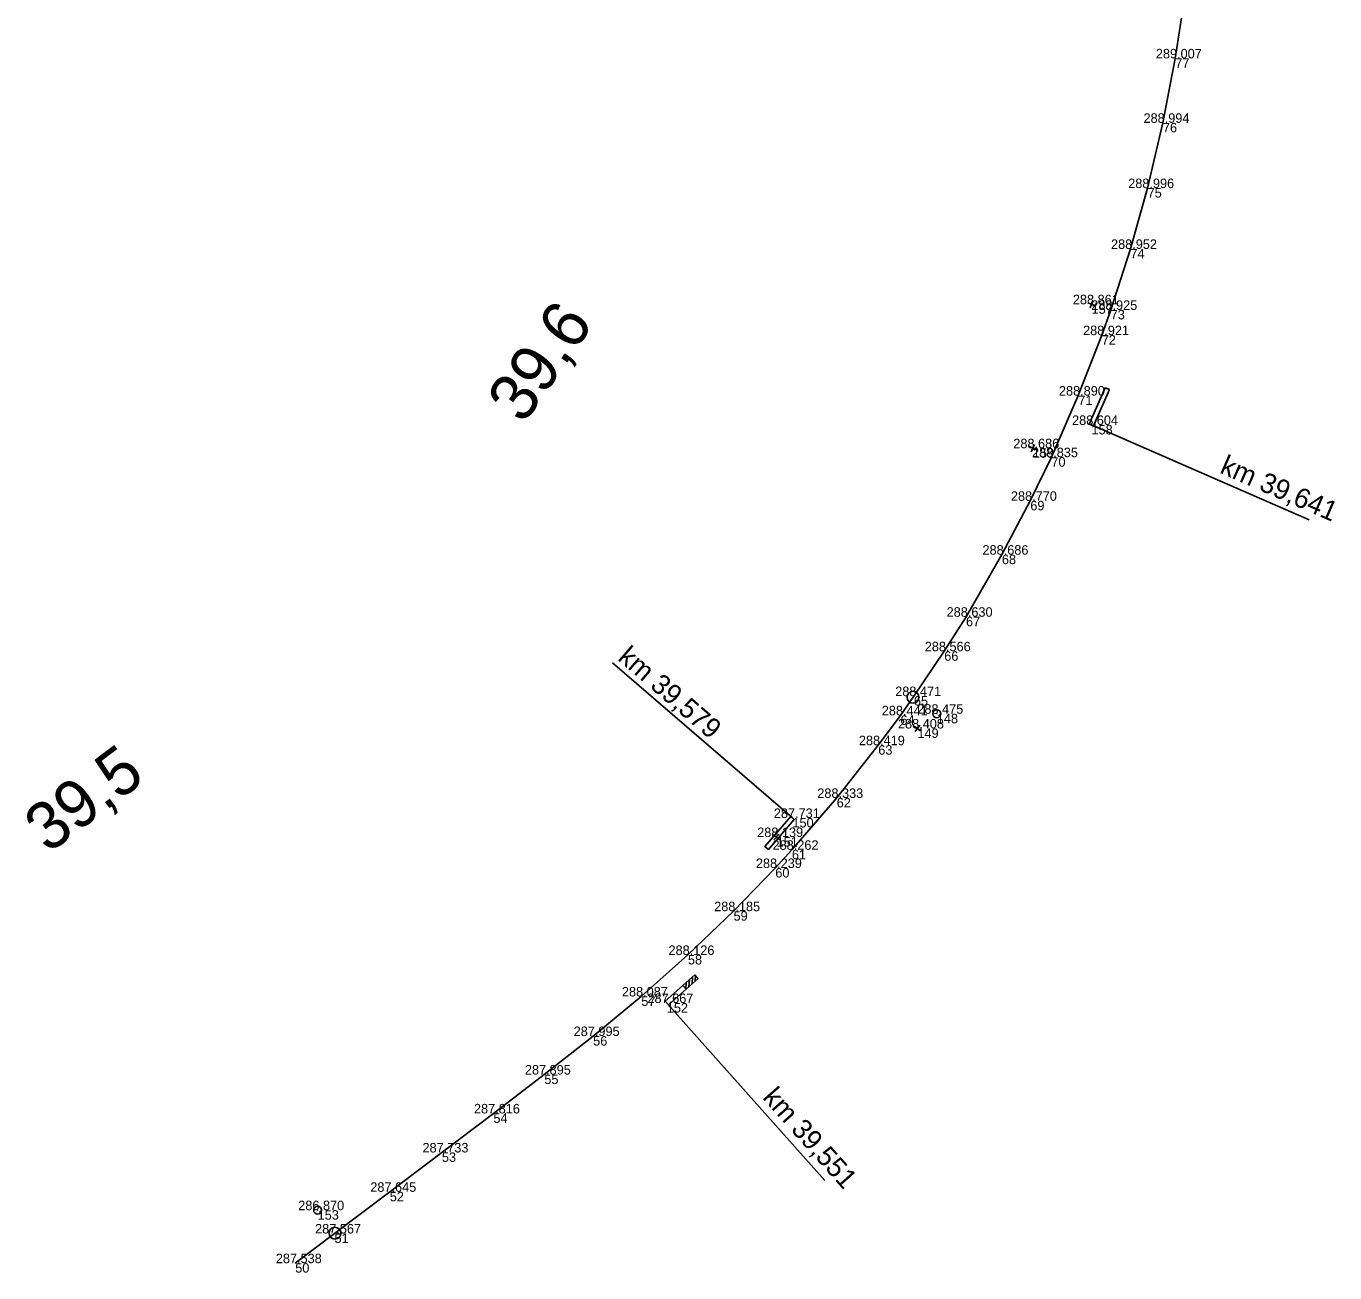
# Model space of a CAD drawing. Extents: x -684938 to -684389, y -1007777 to -1006471.
# Drawn here: x -684554.4 to -684389.1, y -1007776.6 to -1007619.2 of the extents above; entities that cross this region are included whole.
import ezdxf

# ---------------------------------------------------------------- set-up
doc = ezdxf.new("R2010")
doc.units = 0
for name, color, linetype in [('Vrstva 1', 7, 'Continuous'), ('Vrstva 6', 7, 'Continuous'), ('Vrstva 60', 7, 'Continuous'), ('Vrstva 61', 7, 'Continuous'), ('Vrstva 7', 7, 'Continuous'), ('Vrstva 9', 7, 'Continuous')]:
    doc.layers.add(name, color=color, linetype=linetype)

msp = doc.modelspace()

# ---------------------------------------------------------------- linework, layer by layer
at = {"layer": 'Vrstva 1'}
msp.add_lwpolyline([(-684520.41, -1007775.41), (-684515.45, -1007771.66), (-684508.47, -1007766.4), (-684501.89, -1007761.43), (-684495.39, -1007756.5), (-684488.96, -1007751.59), (-684482.79, -1007746.73), (-684476.71, -1007741.73), (-684470.82, -1007736.49), (-684465.06, -1007730.96), (-684459.79, -1007725.51), (-684457.7, -1007723.21), (-684452.04, -1007716.66), (-684446.79, -1007710), (-684443.99, -1007706.23), (-684442.29, -1007703.8), (-684438.46, -1007698.14), (-684435.71, -1007693.78), (-684431.18, -1007685.94), (-684427.59, -1007679.14), (-684424.93, -1007673.63), (-684421.53, -1007665.85), (-684418.57, -1007658.22), (-684417.44, -1007655.03), (-684414.95, -1007647.33), (-684412.78, -1007639.65), (-684410.85, -1007631.41), (-684409.29, -1007623.27), (-684408.06, -1007615.14)], dxfattribs=at)
at = {"layer": 'Vrstva 6'}
for p, q in [((-684470.69, -1007740.47), (-684470.64, -1007739.63)), ((-684470.3, -1007740.12), (-684470.25, -1007739.28)), ((-684469.9, -1007739.77), (-684469.86, -1007739.12)), ((-684471.08, -1007740.75), (-684471.04, -1007739.98)), ((-684453.55, -1007764.98), (-684473.49, -1007742.56))]:
    msp.add_line(p, q, dxfattribs=at)
msp.add_lwpolyline([(-684472.89, -1007743.23), (-684473.29, -1007742.79), (-684473.69, -1007742.34), (-684469.95, -1007739.02), (-684469.55, -1007739.46), (-684473.29, -1007742.79)], dxfattribs=at)
msp.add_lwpolyline([(-684471.05, -1007740.79), (-684471.45, -1007740.34), (-684469.95, -1007739.02), (-684469.55, -1007739.46)], close=True, dxfattribs=at)
at = {"layer": 'Vrstva 60'}
for p, q in [((-684409.29, -1007623.27), (-684409.29, -1007623.27)), ((-684410.85, -1007631.41), (-684410.85, -1007631.41)), ((-684412.78, -1007639.65), (-684412.78, -1007639.65)), ((-684414.95, -1007647.33), (-684414.95, -1007647.33)), ((-684419.86, -1007654.32), (-684419.86, -1007654.32)), ((-684417.44, -1007655.03), (-684417.44, -1007655.03)), ((-684418.57, -1007658.22), (-684418.57, -1007658.22)), ((-684421.53, -1007665.85), (-684421.53, -1007665.85)), ((-684419.87, -1007669.56), (-684419.87, -1007669.56)), ((-684427.28, -1007672.5), (-684427.28, -1007672.5)), ((-684424.93, -1007673.63), (-684424.93, -1007673.63)), ((-684427.59, -1007679.14), (-684427.59, -1007679.14)), ((-684431.18, -1007685.94), (-684431.18, -1007685.94)), ((-684435.71, -1007693.78), (-684435.71, -1007693.78)), ((-684438.46, -1007698.14), (-684438.46, -1007698.14)), ((-684442.29, -1007703.8), (-684442.29, -1007703.8)), ((-684443.99, -1007706.23), (-684443.99, -1007706.23)), ((-684439.4, -1007706.03), (-684439.4, -1007706.03)), ((-684441.85, -1007707.89), (-684441.85, -1007707.89)), ((-684446.79, -1007710), (-684446.79, -1007710)), ((-684452.04, -1007716.66), (-684452.04, -1007716.66)), ((-684457.63, -1007719.19), (-684457.63, -1007719.19)), ((-684459.63, -1007721.6), (-684459.63, -1007721.6)), ((-684457.7, -1007723.21), (-684457.7, -1007723.21)), ((-684459.79, -1007725.51), (-684459.79, -1007725.51)), ((-684465.06, -1007730.96), (-684465.06, -1007730.96)), ((-684470.82, -1007736.49), (-684470.82, -1007736.49)), ((-684476.71, -1007741.73), (-684476.71, -1007741.73)), ((-684473.49, -1007742.56), (-684473.49, -1007742.56)), ((-684482.79, -1007746.73), (-684482.79, -1007746.73)), ((-684488.96, -1007751.59), (-684488.96, -1007751.59)), ((-684495.39, -1007756.5), (-684495.39, -1007756.5)), ((-684501.89, -1007761.43), (-684501.89, -1007761.43)), ((-684508.47, -1007766.4), (-684508.47, -1007766.4)), ((-684517.58, -1007768.72), (-684517.58, -1007768.72)), ((-684515.45, -1007771.66), (-684515.45, -1007771.66)), ((-684520.41, -1007775.41), (-684520.41, -1007775.41))]:
    msp.add_line(p, q, dxfattribs=at)
at = {"layer": 'Vrstva 7'}
for p, q in [((-684420.33, -1007654.15), (-684419.39, -1007654.48)), ((-684420.03, -1007654.79), (-684419.69, -1007653.84)), ((-684427.74, -1007672.3), (-684426.83, -1007672.7)), ((-684427.48, -1007672.96), (-684427.08, -1007672.04)), ((-684439.43, -1007706.07), (-684439.37, -1007705.99)), ((-684442.25, -1007707.59), (-684441.45, -1007708.19)), ((-684442.15, -1007708.29), (-684441.55, -1007707.49)), ((-684460, -1007721.27), (-684459.26, -1007721.94)), ((-684459.97, -1007721.97), (-684459.29, -1007721.23)), ((-684517.62, -1007768.75), (-684517.54, -1007768.69))]:
    msp.add_line(p, q, dxfattribs=at)
for centre, radius in [((-684442.4, -1007703.94), 0.75), ((-684439.4, -1007706.03), 0.5), ((-684517.58, -1007768.72), 0.5), ((-684515.39, -1007771.62), 0.75)]:
    msp.add_circle(centre, radius, dxfattribs=at)
at = {"layer": 'Vrstva 9'}
for p, q in [((-684392.38, -1007681.56), (-684419.87, -1007669.56)), ((-684480.33, -1007699.58), (-684457.63, -1007719.19))]:
    msp.add_line(p, q, dxfattribs=at)
for points in [[(-684419.05, -1007669.92), (-684419.6, -1007669.68), (-684420.15, -1007669.44), (-684418.15, -1007664.86), (-684417.6, -1007665.1), (-684419.6, -1007669.68)], [(-684458.31, -1007718.6), (-684457.85, -1007718.99), (-684457.4, -1007719.38), (-684460.67, -1007723.17), (-684461.12, -1007722.78), (-684457.85, -1007718.99)]]:
    msp.add_lwpolyline(points, dxfattribs=at)

# ---------------------------------------------------------------- texts
at = {"layer": 'Vrstva 6'}
msp.add_text('km 39,551', height=2.5, rotation=311.6456, dxfattribs=at).set_placement((-684461.5, -1007754.56))
at = {"layer": 'Vrstva 60'}
for s, p in [('77', (-684409.29, -1007624.47)), ('76', (-684410.85, -1007632.61)), ('75', (-684412.78, -1007640.85)), ('74', (-684414.95, -1007648.53)), ('157', (-684419.86, -1007655.52)), ('73', (-684417.44, -1007656.23)), ('72', (-684418.57, -1007659.42)), ('71', (-684421.53, -1007667.05)), ('158', (-684419.87, -1007670.76)), ('159', (-684427.28, -1007673.7)), ('70', (-684424.93, -1007674.83)), ('69', (-684427.59, -1007680.34)), ('68', (-684431.18, -1007687.14)), ('67', (-684435.71, -1007694.98)), ('66', (-684438.46, -1007699.34)), ('65', (-684442.29, -1007705)), ('64', (-684443.99, -1007707.43)), ('148', (-684439.4, -1007707.23)), ('149', (-684441.85, -1007709.09)), ('63', (-684446.79, -1007711.2)), ('62', (-684452.04, -1007717.86)), ('150', (-684457.63, -1007720.39)), ('151', (-684459.63, -1007722.8)), ('61', (-684457.7, -1007724.41)), ('60', (-684459.79, -1007726.71)), ('59', (-684465.06, -1007732.16)), ('58', (-684470.82, -1007737.69)), ('57', (-684476.71, -1007742.93)), ('152', (-684473.49, -1007743.76)), ('56', (-684482.79, -1007747.94)), ('55', (-684488.96, -1007752.79)), ('54', (-684495.39, -1007757.7)), ('53', (-684501.89, -1007762.62)), ('52', (-684508.47, -1007767.6)), ('153', (-684517.58, -1007769.92)), ('51', (-684515.45, -1007772.86)), ('50', (-684520.41, -1007776.61))]:
    msp.add_text(s, height=1.2, dxfattribs=at).set_placement(p)
at = {"layer": 'Vrstva 61'}
for s, p in [('289.007', (-684411.74, -1007623.27)), ('288.994', (-684413.3, -1007631.41)), ('288.996', (-684415.23, -1007639.65)), ('288.952', (-684417.4, -1007647.33)), ('288.861', (-684422.22, -1007654.32)), ('288.925', (-684419.89, -1007655.03)), ('288.921', (-684420.93, -1007658.22)), ('288.890', (-684423.98, -1007665.85)), ('288.604', (-684422.32, -1007669.56)), ('288.686', (-684429.74, -1007672.5)), ('288.835', (-684427.38, -1007673.63)), ('288.770', (-684430.04, -1007679.14)), ('288.686', (-684433.63, -1007685.94)), ('288.630', (-684438.16, -1007693.78)), ('288.566', (-684440.92, -1007698.14)), ('288.471', (-684444.65, -1007703.8)), ('288.441', (-684446.35, -1007706.23)), ('288.475', (-684441.86, -1007706.03)), ('288.408', (-684444.3, -1007707.89)), ('288.419', (-684449.24, -1007710)), ('288.333', (-684454.49, -1007716.66)), ('287.731', (-684459.98, -1007719.19)), ('288.139', (-684462.08, -1007721.6)), ('288.262', (-684460.14, -1007723.21)), ('288.239', (-684462.24, -1007725.51)), ('288.185', (-684467.51, -1007730.96)), ('288.126', (-684473.28, -1007736.49)), ('288.087', (-684479.16, -1007741.73)), ('287.667', (-684475.94, -1007742.56)), ('287.995', (-684485.25, -1007746.73)), ('287.895', (-684491.41, -1007751.59)), ('287.816', (-684497.84, -1007756.5)), ('287.733', (-684504.34, -1007761.43)), ('287.645', (-684510.93, -1007766.4)), ('286.870', (-684520.03, -1007768.72)), ('287.567', (-684517.9, -1007771.66)), ('287.538', (-684522.86, -1007775.41))]:
    msp.add_text(s, height=1.2, dxfattribs=at).set_placement(p)
at = {"layer": 'Vrstva 7'}
for s, rotation, p in [('39,6', 55.0713, (-684491.59, -1007669.59)), ('39,5', 37.0391, (-684551.59, -1007723.77))]:
    msp.add_text(s, height=6, rotation=rotation, dxfattribs=at).set_placement(p)
at = {"layer": 'Vrstva 9'}
for s, rotation, p in [('km 39,641', 336.4162, (-684403.79, -1007675.56)), ('km 39,579', 319.197, (-684479.8, -1007699.15))]:
    msp.add_text(s, height=2.5, rotation=rotation, dxfattribs=at).set_placement(p)

doc.saveas('drawing.dxf')
